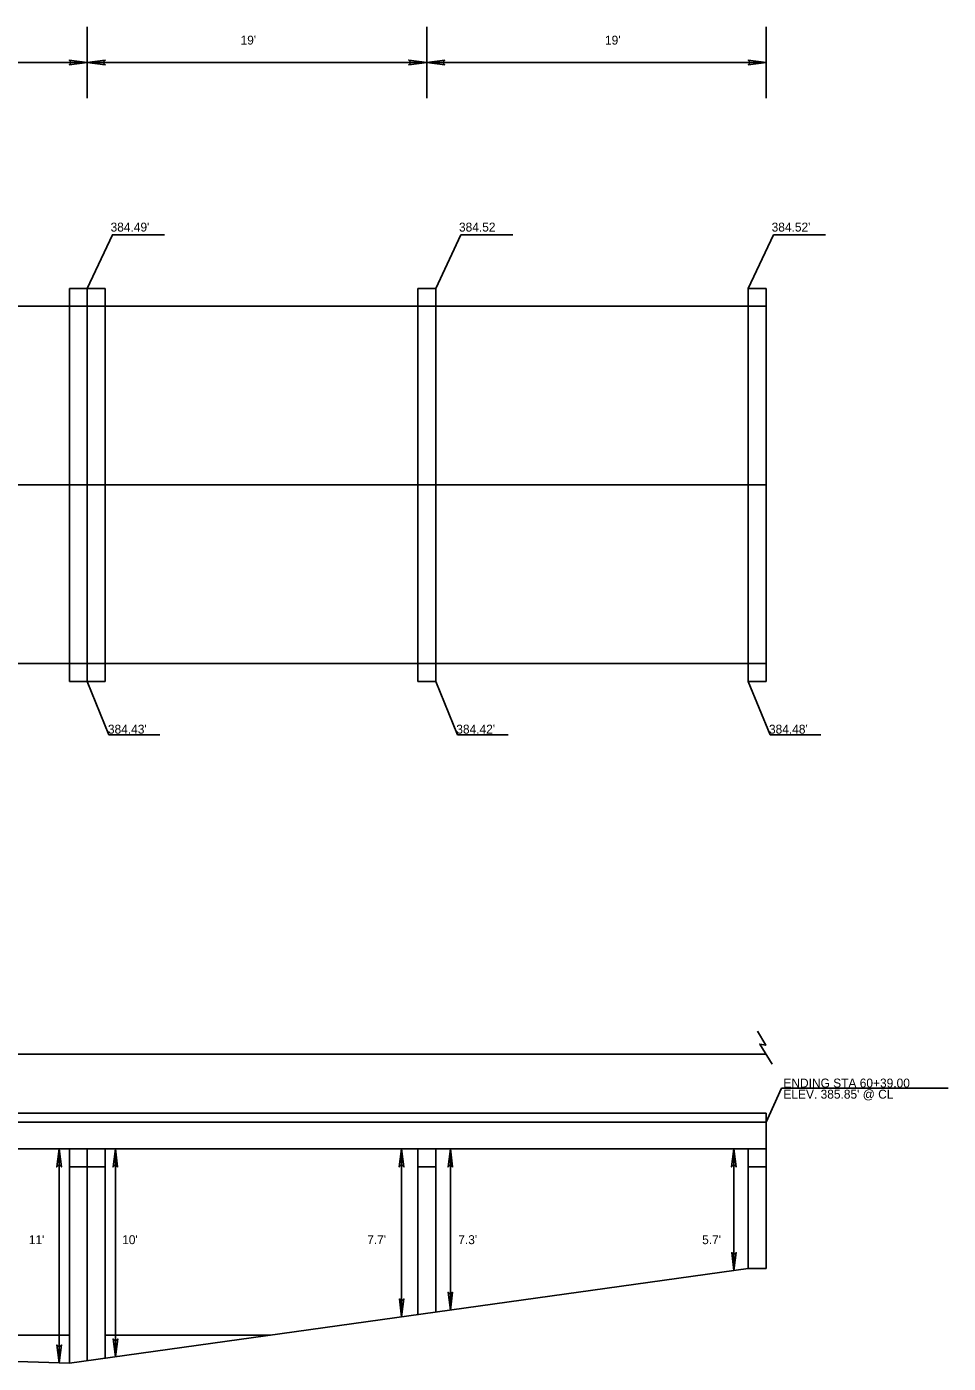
# Model space of a CAD drawing. Extents: x 1189978 to 1314812, y 571533 to 629339.
# Drawn here: x 1228021 to 1228537, y 622517 to 623265 of the extents above; entities that cross this region are included whole.
import ezdxf

# ---------------------------------------------------------------- set-up
doc = ezdxf.new("R2010")
doc.units = 0
doc.layers.add('SURVEY - PROFILE - Drainage - Bridge Hydraulic Data with Text', color=7, linetype='Continuous')

msp = doc.modelspace()

# ---------------------------------------------------------------- linework, layer by layer
at = {"layer": 'SURVEY - PROFILE - Drainage - Bridge Hydraulic Data with Text'}
for p, q in [((1228055.13, 623225.39), (1228055.13, 623265.39)), ((1228245.13, 623225.39), (1228245.13, 623265.39)), ((1228435.13, 623225.39), (1228435.13, 623265.39)), ((1227535.13, 623245.39), (1228435.13, 623245.39)), ((1228055.13, 623118.91), (1228069.16, 623148.91)), ((1228055.13, 623118.91), (1228069.16, 623148.91)), ((1228069.13, 623148.91), (1228098.37, 623148.91)), ((1228069.13, 623148.91), (1228098.37, 623148.91)), ((1228250.13, 623118.91), (1228264.16, 623148.91)), ((1228250.13, 623118.91), (1228264.16, 623148.91)), ((1228264.13, 623148.91), (1228293.37, 623148.91)), ((1228264.13, 623148.91), (1228293.37, 623148.91)), ((1228425.13, 623118.91), (1228439.16, 623148.91)), ((1228425.13, 623118.91), (1228439.16, 623148.91)), ((1228439.13, 623148.91), (1228468.37, 623148.91)), ((1228439.13, 623148.91), (1228468.37, 623148.91)), ((1228045.13, 623118.91), (1228045.13, 622898.91)), ((1228045.13, 623118.91), (1228065.13, 623118.91)), ((1228055.13, 623118.91), (1228055.13, 622898.91)), ((1228065.13, 623118.91), (1228065.13, 622898.91)), ((1228240.13, 623118.91), (1228240.13, 622898.91)), ((1228240.13, 623118.91), (1228250.13, 623118.91)), ((1228250.13, 623118.91), (1228250.13, 622898.91)), ((1228425.13, 623118.91), (1228425.13, 622898.91)), ((1228425.13, 623118.91), (1228435.13, 623118.91)), ((1228435.13, 623118.91), (1228435.13, 622898.91)), ((1227535.13, 623108.91), (1228435.13, 623108.91)), ((1227535.13, 623008.91), (1228435.13, 623008.91)), ((1227535.13, 622908.91), (1228435.13, 622908.91)), ((1228045.13, 622898.91), (1228065.13, 622898.91)), ((1228067.29, 622868.91), (1228055.13, 622898.91)), ((1228067.29, 622868.91), (1228055.13, 622898.91)), ((1228240.13, 622898.91), (1228250.13, 622898.91)), ((1228262.29, 622868.91), (1228250.13, 622898.91)), ((1228262.29, 622868.91), (1228250.13, 622898.91)), ((1228425.13, 622898.91), (1228435.13, 622898.91)), ((1228437.29, 622868.91), (1228425.13, 622898.91)), ((1228437.29, 622868.91), (1228425.13, 622898.91)), ((1228067.29, 622868.91), (1228095.71, 622868.91)), ((1228067.29, 622868.91), (1228095.71, 622868.91)), ((1228262.29, 622868.91), (1228290.71, 622868.91)), ((1228262.29, 622868.91), (1228290.71, 622868.91)), ((1228437.29, 622868.91), (1228465.71, 622868.91)), ((1228437.29, 622868.91), (1228465.71, 622868.91)), ((1227535.13, 622690.27), (1228435.13, 622690.27)), ((1228443.7, 622671.17), (1228435.13, 622652.17)), ((1228443.7, 622671.17), (1228435.13, 622652.17)), ((1228443.68, 622671.17), (1228537.03, 622671.17)), ((1228443.68, 622671.17), (1228537.03, 622671.17)), ((1227535.13, 622657.17), (1228435.13, 622657.17)), ((1228435.13, 622657.17), (1228435.13, 622570.17)), ((1227535.13, 622652.17), (1228435.13, 622652.17)), ((1227535.13, 622637.17), (1228435.13, 622637.17)), ((1228039.39, 622637.17), (1228039.39, 622517.36)), ((1228045.13, 622637.17), (1228045.13, 622627.17)), ((1228055.13, 622637.17), (1228055.13, 622627.17)), ((1228065.13, 622637.17), (1228065.13, 622627.17)), ((1228070.87, 622637.17), (1228070.87, 622520.76)), ((1228231.08, 622637.17), (1228231.08, 622543.1)), ((1228240.13, 622637.17), (1228240.13, 622627.17)), ((1228250.13, 622637.17), (1228250.13, 622627.17)), ((1228258.34, 622637.17), (1228258.34, 622546.91)), ((1228417.06, 622637.17), (1228417.06, 622569.04)), ((1228425.13, 622637.17), (1228425.13, 622627.17)), ((1228045.13, 622627.17), (1228065.13, 622627.17)), ((1228045.13, 622627.17), (1228045.13, 622517.17)), ((1228055.13, 622627.17), (1228055.13, 622518.56)), ((1228240.13, 622627.17), (1228250.13, 622627.17)), ((1228240.13, 622627.17), (1228240.13, 622544.37)), ((1228250.13, 622627.17), (1228250.13, 622545.76)), ((1228425.13, 622627.17), (1228435.13, 622627.17)), ((1228425.13, 622627.17), (1228425.13, 622570.17)), ((1228425.13, 622570.17), (1228045.13, 622517.17)), ((1228425.13, 622570.17), (1228435.13, 622570.17)), ((1227735.13, 622532.87), (1228045.13, 622532.87)), ((1228065.13, 622532.87), (1228157.7, 622532.87)), ((1227735.13, 622527.17), (1228045.13, 622517.17))]:
    msp.add_line(p, q, dxfattribs=at)
for points in [[(1228055.13, 623245.39), (1228045.08, 623244.14), (1228046.38, 623245.39), (1228045.08, 623246.69)], [(1228055.13, 623245.39), (1228045.08, 623244.14), (1228046.38, 623245.39), (1228045.08, 623246.69)], [(1228055.13, 623245.39), (1228065.18, 623246.64), (1228063.88, 623245.39), (1228065.18, 623244.09)], [(1228055.13, 623245.39), (1228065.18, 623246.64), (1228063.88, 623245.39), (1228065.18, 623244.09)], [(1228245.13, 623245.39), (1228235.08, 623244.14), (1228236.38, 623245.39), (1228235.08, 623246.69)], [(1228245.13, 623245.39), (1228235.08, 623244.14), (1228236.38, 623245.39), (1228235.08, 623246.69)], [(1228245.13, 623245.39), (1228255.18, 623246.64), (1228253.88, 623245.39), (1228255.18, 623244.09)], [(1228245.13, 623245.39), (1228255.18, 623246.64), (1228253.88, 623245.39), (1228255.18, 623244.09)], [(1228435.13, 623245.39), (1228425.08, 623244.14), (1228426.38, 623245.39), (1228425.08, 623246.69)], [(1228435.13, 623245.39), (1228425.08, 623244.14), (1228426.38, 623245.39), (1228425.08, 623246.69)], [(1228039.39, 622637.17), (1228040.64, 622627.12), (1228039.39, 622628.42), (1228038.09, 622627.12)], [(1228039.39, 622637.17), (1228040.64, 622627.12), (1228039.39, 622628.42), (1228038.09, 622627.12)], [(1228070.87, 622637.17), (1228072.12, 622627.12), (1228070.87, 622628.42), (1228069.57, 622627.12)], [(1228070.87, 622637.17), (1228072.12, 622627.12), (1228070.87, 622628.42), (1228069.57, 622627.12)], [(1228231.08, 622637.17), (1228232.33, 622627.12), (1228231.08, 622628.42), (1228229.78, 622627.12)], [(1228231.08, 622637.17), (1228232.33, 622627.12), (1228231.08, 622628.42), (1228229.78, 622627.12)], [(1228258.34, 622637.17), (1228259.59, 622627.12), (1228258.34, 622628.42), (1228257.04, 622627.12)], [(1228258.34, 622637.17), (1228259.59, 622627.12), (1228258.34, 622628.42), (1228257.04, 622627.12)], [(1228417.06, 622637.17), (1228418.31, 622627.12), (1228417.06, 622628.42), (1228415.76, 622627.12)], [(1228417.06, 622637.17), (1228418.31, 622627.12), (1228417.06, 622628.42), (1228415.76, 622627.12)], [(1228417.06, 622569.04), (1228415.81, 622579.09), (1228417.06, 622577.79), (1228418.36, 622579.09)], [(1228417.06, 622569.04), (1228415.81, 622579.09), (1228417.06, 622577.79), (1228418.36, 622579.09)], [(1228231.08, 622543.1), (1228229.83, 622553.15), (1228231.08, 622551.85), (1228232.38, 622553.15)], [(1228231.08, 622543.1), (1228229.83, 622553.15), (1228231.08, 622551.85), (1228232.38, 622553.15)], [(1228258.34, 622546.91), (1228257.09, 622556.96), (1228258.34, 622555.66), (1228259.64, 622556.96)], [(1228258.34, 622546.91), (1228257.09, 622556.96), (1228258.34, 622555.66), (1228259.64, 622556.96)], [(1228039.39, 622517.36), (1228038.14, 622527.41), (1228039.39, 622526.11), (1228040.69, 622527.41)], [(1228039.39, 622517.36), (1228038.14, 622527.41), (1228039.39, 622526.11), (1228040.69, 622527.41)], [(1228070.87, 622520.76), (1228069.62, 622530.81), (1228070.87, 622529.51), (1228072.17, 622530.81)], [(1228070.87, 622520.76), (1228069.62, 622530.81), (1228070.87, 622529.51), (1228072.17, 622530.81)]]:
    msp.add_lwpolyline(points, close=True, dxfattribs=at)
for points in [[(1228055.13, 623245.39), (1228045.08, 623244.14), (1228046.38, 623245.39), (1228045.08, 623246.69), (1228055.13, 623245.39)], [(1228055.13, 623245.39), (1228045.08, 623244.14), (1228046.38, 623245.39), (1228045.08, 623246.69), (1228055.13, 623245.39)], [(1228055.13, 623245.39), (1228065.18, 623246.64), (1228063.88, 623245.39), (1228065.18, 623244.09), (1228055.13, 623245.39)], [(1228055.13, 623245.39), (1228065.18, 623246.64), (1228063.88, 623245.39), (1228065.18, 623244.09), (1228055.13, 623245.39)], [(1228245.13, 623245.39), (1228235.08, 623244.14), (1228236.38, 623245.39), (1228235.08, 623246.69), (1228245.13, 623245.39)], [(1228245.13, 623245.39), (1228235.08, 623244.14), (1228236.38, 623245.39), (1228235.08, 623246.69), (1228245.13, 623245.39)], [(1228245.13, 623245.39), (1228255.18, 623246.64), (1228253.88, 623245.39), (1228255.18, 623244.09), (1228245.13, 623245.39)], [(1228245.13, 623245.39), (1228255.18, 623246.64), (1228253.88, 623245.39), (1228255.18, 623244.09), (1228245.13, 623245.39)], [(1228435.13, 623245.39), (1228425.08, 623244.14), (1228426.38, 623245.39), (1228425.08, 623246.69), (1228435.13, 623245.39)], [(1228435.13, 623245.39), (1228425.08, 623244.14), (1228426.38, 623245.39), (1228425.08, 623246.69), (1228435.13, 623245.39)], [(1228438.52, 622684.61), (1228431.53, 622695.87), (1228434.91, 622695.22), (1228430.22, 622703.01)], [(1228039.39, 622637.17), (1228040.64, 622627.12), (1228039.39, 622628.42), (1228038.09, 622627.12), (1228039.39, 622637.17)], [(1228039.39, 622637.17), (1228040.64, 622627.12), (1228039.39, 622628.42), (1228038.09, 622627.12), (1228039.39, 622637.17)], [(1228070.87, 622637.17), (1228072.12, 622627.12), (1228070.87, 622628.42), (1228069.57, 622627.12), (1228070.87, 622637.17)], [(1228070.87, 622637.17), (1228072.12, 622627.12), (1228070.87, 622628.42), (1228069.57, 622627.12), (1228070.87, 622637.17)], [(1228231.08, 622637.17), (1228232.33, 622627.12), (1228231.08, 622628.42), (1228229.78, 622627.12), (1228231.08, 622637.17)], [(1228231.08, 622637.17), (1228232.33, 622627.12), (1228231.08, 622628.42), (1228229.78, 622627.12), (1228231.08, 622637.17)], [(1228258.34, 622637.17), (1228259.59, 622627.12), (1228258.34, 622628.42), (1228257.04, 622627.12), (1228258.34, 622637.17)], [(1228258.34, 622637.17), (1228259.59, 622627.12), (1228258.34, 622628.42), (1228257.04, 622627.12), (1228258.34, 622637.17)], [(1228417.06, 622637.17), (1228418.31, 622627.12), (1228417.06, 622628.42), (1228415.76, 622627.12), (1228417.06, 622637.17)], [(1228417.06, 622637.17), (1228418.31, 622627.12), (1228417.06, 622628.42), (1228415.76, 622627.12), (1228417.06, 622637.17)], [(1228065.13, 622627.17), (1228065.13, 622519.96)], [(1228417.06, 622569.04), (1228415.81, 622579.09), (1228417.06, 622577.79), (1228418.36, 622579.09), (1228417.06, 622569.04)], [(1228417.06, 622569.04), (1228415.81, 622579.09), (1228417.06, 622577.79), (1228418.36, 622579.09), (1228417.06, 622569.04)], [(1228231.08, 622543.1), (1228229.83, 622553.15), (1228231.08, 622551.85), (1228232.38, 622553.15), (1228231.08, 622543.1)], [(1228231.08, 622543.1), (1228229.83, 622553.15), (1228231.08, 622551.85), (1228232.38, 622553.15), (1228231.08, 622543.1)], [(1228258.34, 622546.91), (1228257.09, 622556.96), (1228258.34, 622555.66), (1228259.64, 622556.96), (1228258.34, 622546.91)], [(1228258.34, 622546.91), (1228257.09, 622556.96), (1228258.34, 622555.66), (1228259.64, 622556.96), (1228258.34, 622546.91)], [(1228039.39, 622517.36), (1228038.14, 622527.41), (1228039.39, 622526.11), (1228040.69, 622527.41), (1228039.39, 622517.36)], [(1228039.39, 622517.36), (1228038.14, 622527.41), (1228039.39, 622526.11), (1228040.69, 622527.41), (1228039.39, 622517.36)], [(1228070.87, 622520.76), (1228069.62, 622530.81), (1228070.87, 622529.51), (1228072.17, 622530.81), (1228070.87, 622520.76)], [(1228070.87, 622520.76), (1228069.62, 622530.81), (1228070.87, 622529.51), (1228072.17, 622530.81), (1228070.87, 622520.76)]]:
    msp.add_lwpolyline(points, dxfattribs=at)

# ---------------------------------------------------------------- texts
for s, p in [("19'", (1228140.92, 623255.39)), ("19'", (1228344.89, 623255.39)), ("11'", (1228022.41, 622583.85)), ("10'", (1228074.66, 622583.85)), ("7.7'", (1228211.82, 622583.85)), ("7.3'", (1228262.77, 622583.85)), ("5.7'", (1228399.28, 622583.85))]:
    msp.add_text(s, height=5, rotation=359.99999, dxfattribs=at).set_placement(p)
for s, p in [("384.49'", (1228068.17, 623150.72)), ('384.52', (1228263.17, 623150.72)), ("384.52'", (1228438.17, 623150.72)), ("384.43'", (1228066.68, 622869.66)), ("384.42'", (1228261.68, 622869.66)), ("384.48'", (1228436.68, 622869.66)), ('ENDING STA 60+39.00', (1228444.76, 622671.54)), ("ELEV. 385.85' @ CL", (1228444.76, 622665.32))]:
    msp.add_text(s, height=5, dxfattribs=at).set_placement(p)

doc.saveas('drawing.dxf')
